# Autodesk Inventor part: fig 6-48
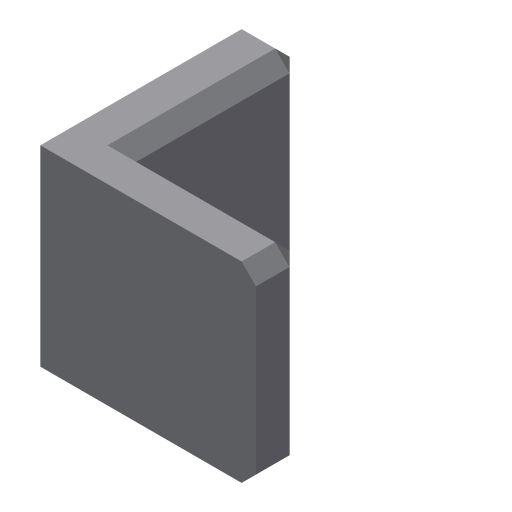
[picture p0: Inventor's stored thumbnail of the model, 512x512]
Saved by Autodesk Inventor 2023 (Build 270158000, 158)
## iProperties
Created: 2009-09
Part Number: fig 6-48
Document SubType Name: Modeling
Designer: Sham
Density: 1 g/cm^3
Material: Generic
Appearance: Default
Author: Sham
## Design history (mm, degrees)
sketch "Sketch1"
  geometry: L1 (1.789, 30)-(1.789, -5); L2 (1.789, -5)-(36.789, -5); L3 (36.789, -5)-(36.789, -15); L4 (36.789, -15)-(-8.211, -15); L5 (-8.211, -15)-(-8.211, 30); L6 (-8.211, 30)-(1.789, 30)
  constraints: 12 end point, 6 perpendicular
  dimensions: "d0" = 10 distance of L5.end L1.start; "d1" = 35 distance of L1.start L1.end; "d2" = 45 distance of L3.end L4.end; "d3" = 10 distance of L2.end L3.end (derived)
extrude "Extrusion1" new body sketch "Sketch1" distance "d4" = 40; taper "d5" = 0 deg
chamfer "Chamfer1" distance "d6" = 3; stored, may be unused: second distance "d7" = 2, angle "d8" = 45 deg
body "Solid1"
other parameters: "d1" = 35
